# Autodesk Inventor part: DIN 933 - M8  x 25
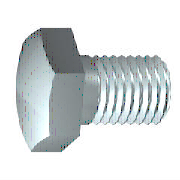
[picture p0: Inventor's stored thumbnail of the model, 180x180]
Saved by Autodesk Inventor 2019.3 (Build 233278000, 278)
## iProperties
Created: 2018-01
Part Number: DIN 933 - M8  x 25
Material: Ocel, měkká
Description: Šestihranný šroub
Document SubType Name: Modeling
Standard: DIN 933
Designer: B-hon
Standards Organization: DIN
Language: cs-CZ
Size Designation: M8  x 25
Categories: <MemberInstance><Categories><Category DisplayName="Spojovací materiál" InternalName="e4da775c-781d-43d5-af7c-5136215cf5a6" Mnemonic="FSTN"><Category DisplayName
Density: 7.85 g/cm^3
Appearance: Pololeštěná
IsCustomPart: 0
Author: B-hon
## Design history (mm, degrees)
sketch "Náčrt1"
  geometry: L1 (0, 5.7)-(0, 3.662); L2 (3.75, 4)-(25, 4); L3 (25, 4)-(25, 0); L4 (25, 0)-(-0.6, 0); L5 (-5.72, 0)-(30.12, 0) reference; L6 (-0.6, 0)-(-0.6, 5.7); L7 (-0.6, 5.7)-(0, 5.7); L8 (3.75, 4)-(2.983, 3.662); L9 (2.983, 3.662)-(0, 3.662); L10 (0, -1.14)-(0, 6.84) reference
  constraints: 16 end point, 2 collinear, 2 perpendicular, 1 parallel
  dimensions: "d0" = 25 distance between parallel lines of L3 L1 (= NLG); "d1" = 21.25 distance from line of L2.start L3 (= GEL); "d2" = 8 diameter of L2 L4 (= GD); "d9" = 0.6001 distance between parallel lines of L6 L1 (computed from SD); "d10" = 11.4 diameter of L7 L4 (= SD2); "d13" = 0.76691 horizontal distance of L2.start L8.end (computed from GAL); "d14" = 7.32342 diameter of L9 L4 (= BDM)
revolve "Těleso" sketch "Náčrt1" stored, may be unused: angle "d12" = 90 deg
sketch "Náčrt2"
  geometry: L1 (0, 7.506)-(6.5, 3.753); L2 (6.5, 3.753)-(6.5, -3.753); L3 (6.5, -3.753)-(0, -7.506); L4 (0, -7.506)-(-6.5, -3.753); L5 (-6.5, -3.753)-(-6.5, 3.753); L6 (-6.5, 3.753)-(0, 7.506); 2 further points
  constraints: 12 end point, 1 coincident, 1 vertical, 11 other
  dimensions: "d11" = 13 distance between parallel lines of L5 L2 (= SW)
extrude "Hlava" join sketch "Náčrt2" distance "d3" = 4.7 (= KOH - SD); taper "d4" = 0 deg
sketch "Náčrt4"
  geometry: L1 (-5.3, 6.5)-(-5.3, 7.506); L2 (-5.3, 7.506)-(-4.72, 7.506); L3 (-4.72, 7.506)-(-5.3, 6.5); L4 (-6.24, 0)-(0.34, 0) reference; L5 (-0.6, 7.506)-(-5.3, 7.506) reference; L6 (-5.3, 3.753)-(-5.3, 7.506) reference
  constraints: 6 end point, 2 collinear, 1 perpendicular, 1 vertical
  dimensions: "d5" = 30 deg angle of L3 L1 (= ANG1); "d19" = 13 diameter of L1.start L4 (= SW0)
revolve "Zkosení1" sketch "Náčrt4" stored, may be unused: angle "d21" = 90 deg
workplane "Work Plane1"
body "Solid1"
feature "Závit" dims "d15" = 21.25 (= GEL), "d16" = 0
chamfer "Zkosení2" distance "d6" = 0.76681 (= -0.5 x SPD + 0.5 x GD); stored, may be unused: second distance "d7" = 0.76691 (computed from GUL), angle "d55" = 45 deg
other parameters: "NLG" = 25 [user parameter; used in 1 equation term], "GD" = 8 (= NND) [user parameter; used in 2 equation terms], "BDM" = 7.32342 [user parameter; used in 1 equation term], "KOH" = 5.3 [user parameter; used in 1 equation term], "GEL" = 21.25 [user parameter; used in 2 equation terms], "SW" = 13 [user parameter; used in 2 equation terms], "SW0" = 13 [user parameter; used in 1 equation term], "SPD" = 6.46637 (= NND - 1.2269 x PTC) [user parameter; used in 1 equation term], "SD2" = 11.4 [user parameter; used in 1 equation term], "SD" = 0.6 [user parameter; used in 2 equation terms], "ANG1" = 30 deg [user parameter; used in 1 equation term], "GAL" = 0.76681 (= 0.61345 x PTC) [user parameter; used in 1 equation term], "GUL" = 0.76681 (= 0.61345 x PTC) [user parameter; used in 1 equation term], "d8" = 0, "RR" = 0.4 [user parameter], "d57" = 0, "d58" = 0, "TPU" = 8 (computed from PTC) [user parameter], "GD1" = 6.46637 (= THREADDIA - 1.2269 x PTC) [user parameter], "THREADDIA" = 8 [user parameter; used in 1 equation term], "TOA" = 30 deg [user parameter], "PTC" = 1.25 [user parameter; used in 5 equation terms], "NND" = 8 [user parameter; used in 2 equation terms], "E0" = 15.015 (= 1.155 x SW) [user parameter]
